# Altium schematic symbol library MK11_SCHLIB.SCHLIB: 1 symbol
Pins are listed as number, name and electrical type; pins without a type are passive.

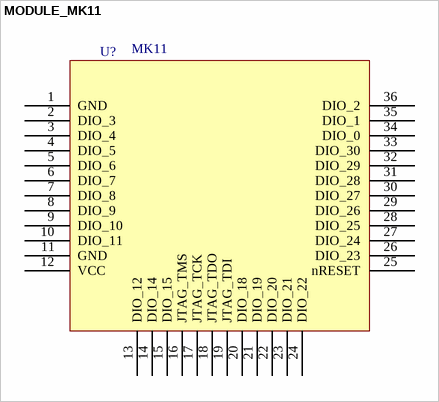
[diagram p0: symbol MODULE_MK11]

## MODULE_MK11
designator U?, comment MK11
footprint PCB_MK11 (25.05mm*17mm)
pins: 1 GND, 2 DIO_3, 3 DIO_4, 4 DIO_5, 5 DIO_6, 6 DIO_7, 7 DIO_8, 8 DIO_9, 9 DIO_10, 10 DIO_11, 11 GND, 12 VCC, 13 DIO_12, 14 DIO_14, 15 DIO_15, 16 JTAG_TMS, 17 JTAG_TCK, 18 JTAG_TDO, 19 JTAG_TDI, 20 DIO_18, 21 DIO_19, 22 DIO_20, 23 DIO_21, 24 DIO_22, 25 nRESET, 26 DIO_23, 27 DIO_24, 28 DIO_25, 29 DIO_26, 30 DIO_27, 31 DIO_28, 32 DIO_29, 33 DIO_30, 34 DIO_0, 35 DIO_1, 36 DIO_2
